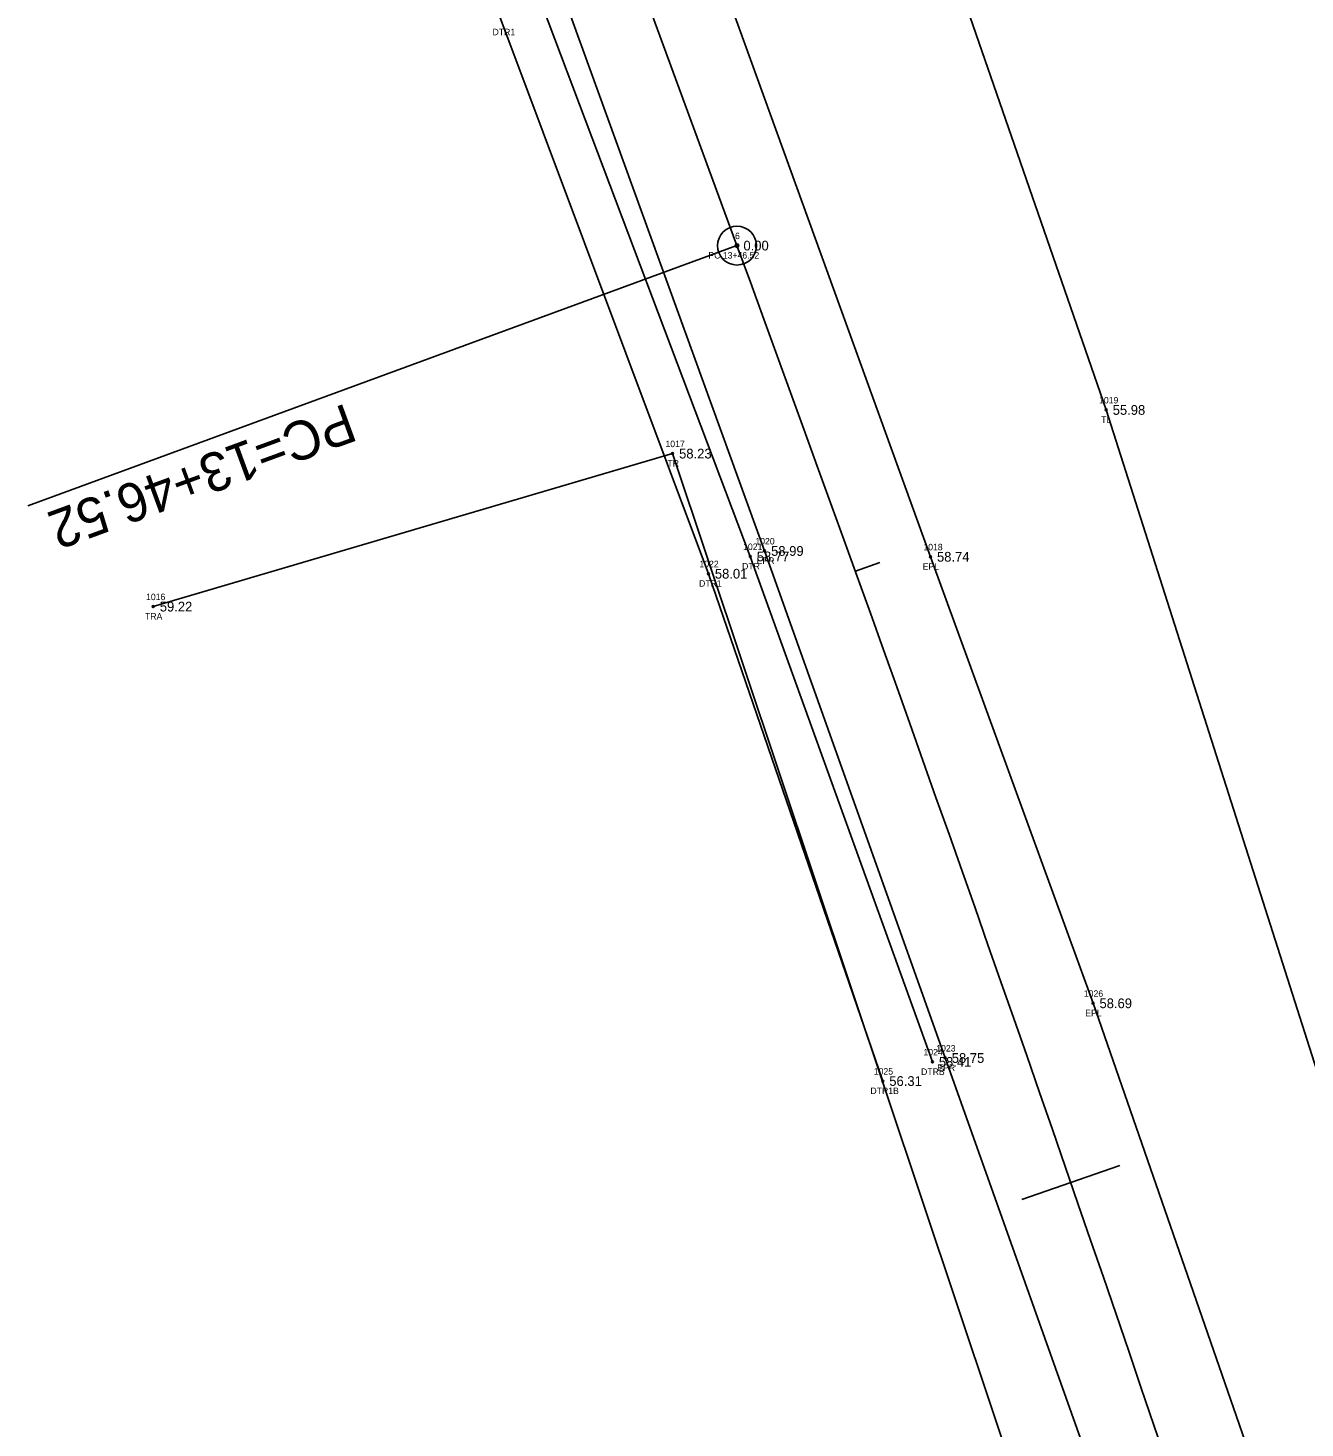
# Model space of a CAD drawing. Extents: x 2396531 to 2397633, y 770203 to 772837.
# Drawn here: x 2396647 to 2396844.1, y 772197.8 to 772413.8 of the extents above; entities that cross this region are included whole.
import ezdxf

# ---------------------------------------------------------------- set-up
doc = ezdxf.new("R2010")
doc.units = 0
for name, color, linetype in [('RD_EX_H2O', 7, 'Continuous'), ('RD_EX_H2O_txCode', 7, 'Continuous'), ('RD_EX_Road', 7, 'Continuous'), ('RD_EX_Road_txCode', 7, 'Continuous'), ('RD_EX_TX_H2O_ELEV', 7, 'Continuous'), ('RD_EX_TX_Road_ELEV', 7, 'Continuous'), ('RD_EX_TX_VEG_ELEV', 7, 'Continuous'), ('RD_EX_VEG', 7, 'Continuous'), ('RD_EX_VEG_txCode', 7, 'Continuous'), ('RD_HC_Cl', 7, 'Continuous'), ('RD_HC_Data', 7, 'Continuous'), ('RD_HC_Data_Tic', 7, 'Continuous'), ('RD_HC_Survey_ELEV', 7, 'Continuous'), ('RD_HC_txCode', 7, 'Continuous'), ('RD_SMD_Locator', 7, 'Continuous')]:
    doc.layers.add(name, color=color, linetype=linetype)

msp = doc.modelspace()

# ---------------------------------------------------------------- linework, layer by layer
at = {"layer": 'RD_EX_H2O'}
for points in [[(2396654.89, 772610.44), (2396689.53, 772515.4), (2396726.4, 772417.15), (2396758.49, 772332.26), (2396786.59, 772254.26)], [(2396647.52, 772607.47), (2396683.51, 772512.21), (2396720.14, 772414.69), (2396752.02, 772329.6), (2396778.94, 772251.31)]]:
    msp.add_lwpolyline(points, dxfattribs=at)
at = {"layer": 'RD_EX_Road'}
for points in [[(2396680.92, 772617.84), (2396715.6, 772525.73), (2396750.68, 772430.62), (2396786.3, 772332.21), (2396811.38, 772263.31), (2396839.69, 772181.74), (2396863.75, 772109.83), (2396883.63, 772046.56), (2396889.54, 772027.11), (2396896.25, 772004.37), (2396904.34, 771978.33), (2396908.24, 771964.89), (2396921.74, 771919.68), (2396927.03, 771902.11), (2396950.2, 771821.74), (2396970.47, 771750.68), (2396978.33, 771721.29), (2396990.58, 771675.04), (2397004.94, 771620.49), (2397034.26, 771508.8), (2397061.11, 771410.49), (2397060.64, 771407.04), (2397062.07, 771407.67)], [(2396658.78, 772611.07), (2396693.37, 772516.9), (2396729.65, 772418.78), (2396760.7, 772333.11), (2396788.58, 772254.87), (2396814.65, 772181.57), (2396841.1, 772100.86), (2396861.19, 772037.76), (2396886.09, 771955.71), (2396907.15, 771884.49), (2396928.56, 771811.72), (2396947.65, 771744.09), (2396985.17, 771602.64), (2397011.11, 771504.04), (2397037.95, 771404.25), (2397039, 771401.22)]]:
    msp.add_lwpolyline(points, dxfattribs=at)
at = {"layer": 'RD_EX_VEG'}
for points in [[(2396718.46, 772629.07), (2396813.42, 772354.87), (2396912.88, 772043.07)], [(2396666.35, 772324.52), (2396746.5, 772348.13), (2396878.43, 771953.6), (2396907.83, 771806.94), (2396910.04, 771736.08), (2396945.43, 771592.11), (2397049.51, 771229.15), (2396980.16, 771221.67)]]:
    msp.add_lwpolyline(points, dxfattribs=at)
at = {"layer": 'RD_HC_Cl'}
msp.add_line((2396670.2, 772615.07), (2396756.43, 772380.23), dxfattribs=at)
msp.add_arc((2389304.02, 769643.48), 7939.03, 14.59125, 20.164785, dxfattribs=at)
at = {"layer": 'RD_HC_Data'}
msp.add_line((2396756.43, 772380.23), (2396647.01, 772340.05), dxfattribs=at)
for radius in [3, 0.282]:
    msp.add_circle((2396756.43, 772380.23), radius, dxfattribs=at)
at = {"layer": 'RD_HC_Data_Tic'}
for p, q in [((2396774.7, 772329.97), (2396778.47, 772331.32)), ((2396807.95, 772235.65), (2396815.51, 772238.27)), ((2396807.95, 772235.65), (2396800.39, 772233.04))]:
    msp.add_line(p, q, dxfattribs=at)
at = {"layer": 'RD_SMD_Locator'}
for centre in [(2396756.43, 772380.23), (2396813.42, 772354.87), (2396746.5, 772348.13), (2396758.49, 772332.26), (2396760.7, 772333.11), (2396786.3, 772332.21), (2396752.02, 772329.6), (2396666.35, 772324.52), (2396811.38, 772263.31), (2396788.58, 772254.87), (2396786.59, 772254.26), (2396778.94, 772251.31)]:
    msp.add_circle(centre, 0.15, dxfattribs=at)

# ---------------------------------------------------------------- texts
at = {"layer": 'RD_EX_H2O_txCode'}
for s, p in [('DTR1', (2396718.71, 772412.69)), ('1021', (2396757.38, 772333.26)), ('1022', (2396750.63, 772330.6)), ('DTR', (2396757.22, 772330.26)), ('DTR1', (2396750.58, 772327.6)), ('1024', (2396785.21, 772255.26)), ('1025', (2396777.55, 772252.31)), ('DTRB', (2396784.85, 772252.26)), ('DTR1B', (2396777.03, 772249.31))]:
    msp.add_text(s, height=1, dxfattribs=at).set_placement(p)
at = {"layer": 'RD_EX_Road_txCode'}
for s, p in [('1020', (2396759.27, 772334.11)), ('1018', (2396785.2, 772333.21)), ('EPR', (2396759.47, 772331.11)), ('EPL', (2396785.09, 772330.21)), ('1026', (2396809.97, 772264.31)), ('EPL', (2396810.18, 772261.31)), ('1023', (2396787.19, 772255.87)), ('EPR', (2396787.35, 772252.87))]:
    msp.add_text(s, height=1, dxfattribs=at).set_placement(p)
at = {"layer": 'RD_EX_TX_H2O_ELEV'}
for s, p in [('58.77', (2396759.49, 772331.51)), ('58.01', (2396753.02, 772328.85)), ('58.41', (2396787.59, 772253.51)), ('56.31', (2396779.94, 772250.56))]:
    msp.add_text(s, height=1.5, dxfattribs=at).set_placement(p)
at = {"layer": 'RD_EX_TX_Road_ELEV'}
for s, p in [('58.99', (2396761.7, 772332.36)), ('58.74', (2396787.3, 772331.46)), ('58.69', (2396812.38, 772262.56)), ('58.75', (2396789.58, 772254.12))]:
    msp.add_text(s, height=1.5, dxfattribs=at).set_placement(p)
at = {"layer": 'RD_EX_TX_VEG_ELEV'}
for s, p in [('55.98', (2396814.42, 772354.12)), ('58.23', (2396747.5, 772347.38)), ('59.22', (2396667.35, 772323.77))]:
    msp.add_text(s, height=1.5, dxfattribs=at).set_placement(p)
at = {"layer": 'RD_EX_VEG_txCode'}
for s, p in [('1019', (2396812.31, 772355.87)), ('TL', (2396812.64, 772352.87)), ('1017', (2396745.4, 772349.13)), ('TR', (2396745.7, 772346.13)), ('1016', (2396665.23, 772325.52)), ('TRA', (2396665.07, 772322.52))]:
    msp.add_text(s, height=1, dxfattribs=at).set_placement(p)
at = {"layer": 'RD_HC_Data'}
msp.add_text('PC=13+46.52', height=6, rotation=200.1648, dxfattribs=at).set_placement((2396696.11, 772355.95))
at = {"layer": 'RD_HC_Survey_ELEV'}
msp.add_text('0.00', height=1.5, dxfattribs=at).set_placement((2396757.43, 772379.48))
at = {"layer": 'RD_HC_txCode'}
for s, p in [('6', (2396756.13, 772381.23)), ('PC 13+46.52', (2396752.02, 772378.23))]:
    msp.add_text(s, height=1, dxfattribs=at).set_placement(p)

doc.saveas('drawing.dxf')
